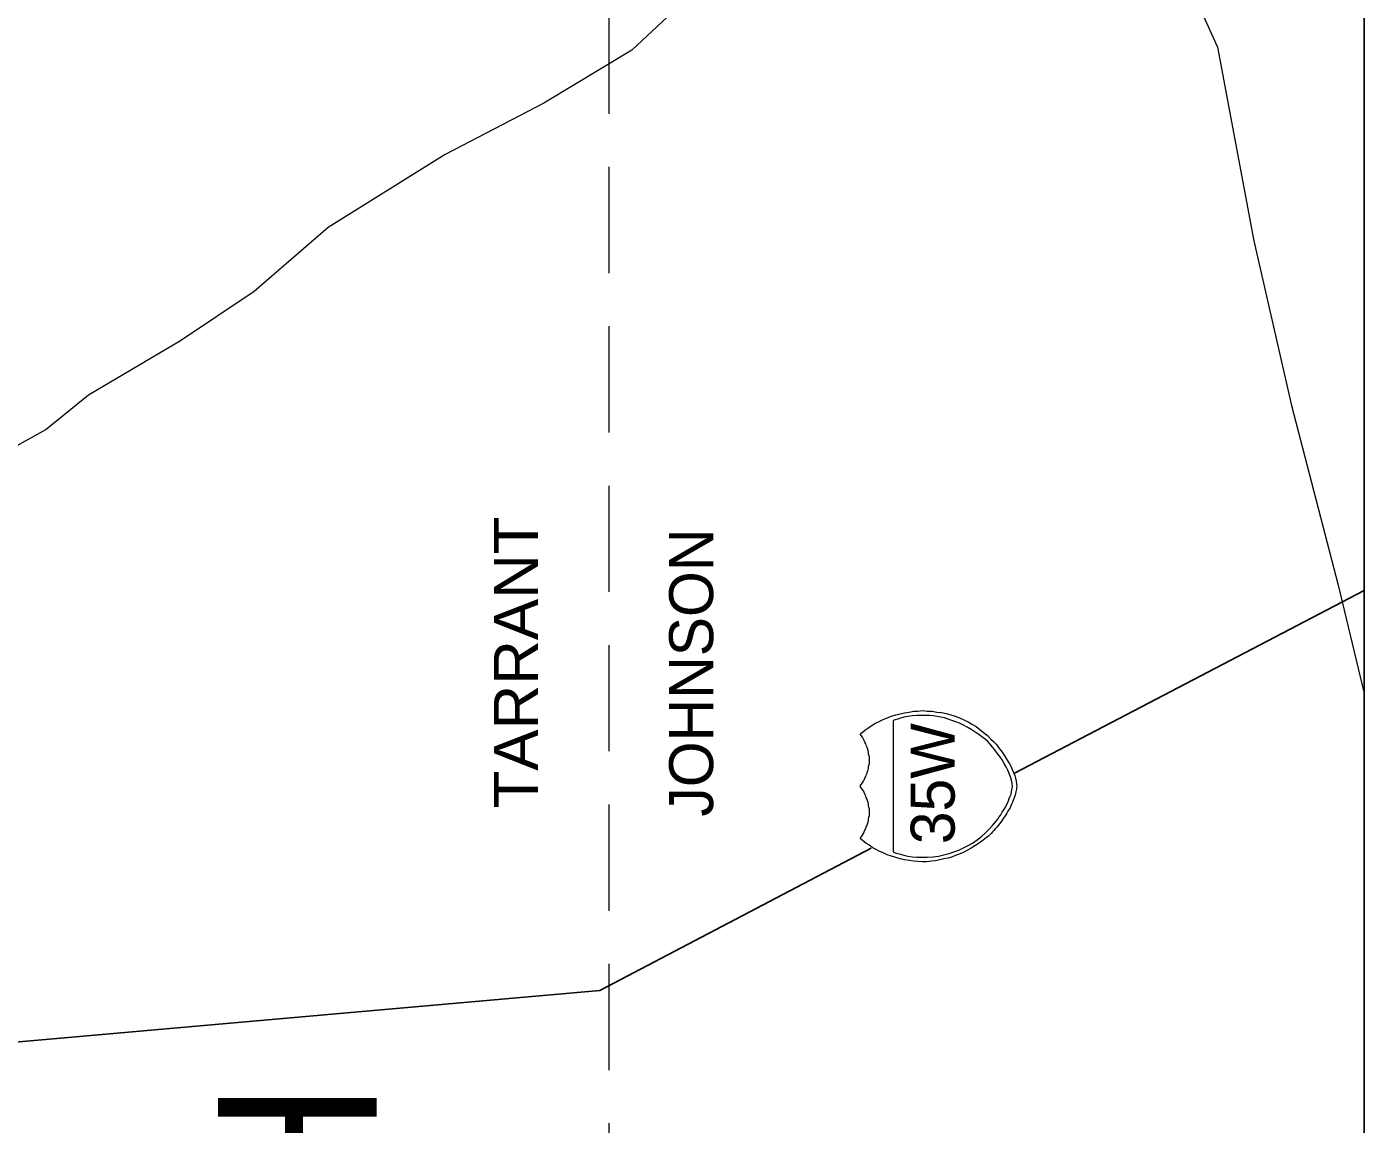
# Model space of a CAD drawing. Extents: x 2363323 to 2367082, y 6956018 to 6980837.
# Drawn here: x 2366064.3 to 2366219.2, y 6980582.6 to 6980709.7 of the extents above; entities that cross this region are included whole.
import ezdxf

# ---------------------------------------------------------------- set-up
doc = ezdxf.new("R2010")
doc.units = 0
doc.header["$LTSCALE"] = 4.1
doc.linetypes.add('MEDIUM_DASHED', pattern=[4.5, 3, -1.5])
doc.layers.add('62', color=7, linetype='Continuous', lineweight=13)
doc.layers.add('63', color=7, linetype='Continuous', lineweight=13)

msp = doc.modelspace()

# ---------------------------------------------------------------- linework, layer by layer
at = {"layer": '62', "linetype": 'MEDIUM_DASHED'}
msp.add_line((2366131.806, 6980385.954), (2366131.805, 6980835.548), dxfattribs=at)
at = {"layer": '62', "lineweight": 25}
msp.add_line((2366178.725, 6980623.262), (2366219.249, 6980644.436), dxfattribs=at)
for points in [[(2365753.976, 6980385.954), (2366219.249, 6980385.954), (2366219.249, 6980835.546), (2365753.974, 6980835.546)], [(2365954.874, 6980590.182), (2366003.705, 6980591.15), (2366059.484, 6980591.828), (2366130.702, 6980598.128), (2366162.138, 6980614.575)]]:
    msp.add_lwpolyline(points, dxfattribs=at)
at = {"layer": '62'}
for points in [[(2366094.97, 6980793.962), (2366103.882, 6980788.406), (2366120.534, 6980778.952), (2366139.278, 6980772.878), (2366153.61, 6980769.728), (2366166.728, 6980753.031), (2366176.79, 6980752.894), (2366186.194, 6980736.56), (2366195.014, 6980723.396), (2366202.238, 6980707.329), (2366206.47, 6980684.916), (2366210.836, 6980665.836), (2366216.234, 6980645.043), (2366219.25, 6980632.51)], [(2366168.8, 6980776.882), (2366165.783, 6980768.805), (2366163.94, 6980759.174), (2366160.383, 6980741.87), (2366154.128, 6980731.611), (2366149.72, 6980724.7), (2366143.802, 6980715.788), (2366134.416, 6980706.992), (2366124.222, 6980700.849), (2366112.792, 6980694.908), (2366099.244, 6980686.448), (2366090.672, 6980679.021), (2366082.168, 6980673.328), (2366071.481, 6980667.05), (2366066.596, 6980663.068), (2366053.86, 6980656.002)], [(2366161.328, 6980622.518), (2366161.42, 6980622.699), (2366161.51, 6980622.902), (2366161.576, 6980623.06), (2366161.666, 6980623.262), (2366161.712, 6980623.464), (2366161.778, 6980623.644), (2366161.823, 6980623.824), (2366161.846, 6980624.025), (2366161.89, 6980624.206), (2366161.936, 6980624.409), (2366161.936, 6980624.589), (2366161.936, 6980624.793), (2366161.937, 6980624.972), (2366161.936, 6980625.15), (2366161.89, 6980625.376), (2366161.847, 6980625.534), (2366161.823, 6980625.714), (2366161.78, 6980625.916), (2366161.71, 6980626.119), (2366161.666, 6980626.299), (2366161.577, 6980626.502), (2366161.51, 6980626.682), (2366161.42, 6980626.862), (2366161.33, 6980627.042), (2366161.24, 6980627.222), (2366161.126, 6980627.424), (2366160.99, 6980627.626), (2366160.856, 6980627.808), (2366161.17, 6980628.076), (2366161.508, 6980628.326), (2366161.868, 6980628.572), (2366162.273, 6980628.818), (2366162.656, 6980629.046), (2366163.083, 6980629.27), (2366163.534, 6980629.473), (2366164.007, 6980629.676), (2366164.5, 6980629.856), (2366164.996, 6980630.013), (2366165.514, 6980630.146), (2366166.008, 6980630.26), (2366166.526, 6980630.35), (2366167.044, 6980630.44), (2366167.562, 6980630.463), (2366168.08, 6980630.51), (2366168.642, 6980630.464), (2366169.206, 6980630.44), (2366169.768, 6980630.352), (2366170.286, 6980630.282), (2366170.826, 6980630.194), (2366171.366, 6980630.013), (2366171.885, 6980629.856), (2366172.378, 6980629.676), (2366172.875, 6980629.45), (2366173.368, 6980629.204), (2366173.82, 6980628.933), (2366174.292, 6980628.662), (2366174.742, 6980628.326), (2366175.168, 6980627.986), (2366175.598, 6980627.628), (2366176.001, 6980627.222), (2366176.316, 6980626.929), (2366176.608, 6980626.616), (2366176.901, 6980626.254), (2366177.171, 6980625.916), (2366177.418, 6980625.534), (2366177.666, 6980625.15), (2366177.892, 6980624.79), (2366178.116, 6980624.432), (2366178.318, 6980624.072), (2366178.478, 6980623.712), (2366178.634, 6980623.352), (2366178.77, 6980622.993), (2366178.86, 6980622.676), (2366178.926, 6980622.362), (2366178.971, 6980622.046), (2366178.995, 6980621.776)], [(2366178.995, 6980621.776), (2366178.971, 6980621.596), (2366178.971, 6980621.439), (2366178.95, 6980621.259), (2366178.904, 6980621.103), (2366178.858, 6980620.922), (2366178.815, 6980620.742), (2366178.746, 6980620.516), (2366178.68, 6980620.312), (2366178.59, 6980620.134), (2366178.521, 6980619.932), (2366178.41, 6980619.704), (2366178.32, 6980619.502), (2366178.228, 6980619.278), (2366178.118, 6980619.099), (2366177.981, 6980618.871), (2366177.868, 6980618.648), (2366177.734, 6980618.445), (2366177.598, 6980618.22), (2366177.442, 6980618.019), (2366177.308, 6980617.816), (2366177.171, 6980617.612), (2366176.991, 6980617.412), (2366176.856, 6980617.208), (2366176.698, 6980617.028), (2366176.518, 6980616.826), (2366176.361, 6980616.645), (2366176.205, 6980616.465), (2366176.024, 6980616.308), (2366175.844, 6980616.105), (2366175.688, 6980615.948), (2366175.506, 6980615.812), (2366175.326, 6980615.655), (2366174.966, 6980615.385), (2366174.537, 6980615.092), (2366174.134, 6980614.846), (2366173.728, 6980614.599), (2366173.302, 6980614.352), (2366172.875, 6980614.125), (2366172.448, 6980613.924), (2366171.996, 6980613.766), (2366171.546, 6980613.585), (2366171.074, 6980613.428), (2366170.578, 6980613.338), (2366170.106, 6980613.225), (2366169.611, 6980613.112), (2366169.137, 6980613.068), (2366168.597, 6980613.024), (2366168.08, 6980612.998), (2366167.56, 6980613.045), (2366167.043, 6980613.09), (2366166.526, 6980613.158), (2366166.008, 6980613.246), (2366165.513, 6980613.36), (2366164.996, 6980613.495), (2366164.502, 6980613.652), (2366164.006, 6980613.81), (2366163.533, 6980614.036), (2366163.083, 6980614.236), (2366162.657, 6980614.462), (2366162.273, 6980614.686), (2366161.866, 6980614.958), (2366161.51, 6980615.16), (2366161.172, 6980615.43), (2366160.856, 6980615.7), (2366160.99, 6980615.88), (2366161.126, 6980616.082), (2366161.24, 6980616.285), (2366161.33, 6980616.465), (2366161.42, 6980616.668), (2366161.508, 6980616.848), (2366161.577, 6980617.05), (2366161.666, 6980617.232), (2366161.71, 6980617.41), (2366161.778, 6980617.59), (2366161.823, 6980617.792), (2366161.847, 6980617.972), (2366161.89, 6980618.199), (2366161.937, 6980618.355), (2366161.937, 6980618.536), (2366161.936, 6980618.76), (2366161.936, 6980618.94), (2366161.936, 6980619.12), (2366161.892, 6980619.322), (2366161.847, 6980619.502), (2366161.823, 6980619.682), (2366161.778, 6980619.862), (2366161.71, 6980620.088), (2366161.667, 6980620.269), (2366161.576, 6980620.449), (2366161.508, 6980620.629), (2366161.418, 6980620.832), (2366161.328, 6980621.034), (2366161.238, 6980621.214), (2366161.127, 6980621.394), (2366160.992, 6980621.576), (2366160.857, 6980621.776), (2366160.99, 6980621.956), (2366161.126, 6980622.136), (2366161.238, 6980622.34), (2366161.328, 6980622.518)]]:
    msp.add_lwpolyline(points, dxfattribs=at)
msp.add_lwpolyline([(2366164.703, 6980629.383), (2366164.704, 6980614.148), (2366164.928, 6980614.059), (2366165.22, 6980613.968), (2366165.534, 6980613.878), (2366165.942, 6980613.788), (2366166.392, 6980613.676), (2366166.908, 6980613.585), (2366167.448, 6980613.54), (2366168.081, 6980613.538), (2366168.687, 6980613.542), (2366169.342, 6980613.585), (2366169.948, 6980613.675), (2366170.556, 6980613.81), (2366171.164, 6980613.968), (2366171.726, 6980614.148), (2366172.311, 6980614.35), (2366172.851, 6980614.62), (2366173.368, 6980614.89), (2366173.886, 6980615.184), (2366174.404, 6980615.544), (2366174.898, 6980615.902), (2366175.347, 6980616.33), (2366175.8, 6980616.78), (2366176.205, 6980617.23), (2366176.608, 6980617.726), (2366176.812, 6980617.95), (2366176.97, 6980618.22), (2366177.172, 6980618.468), (2366177.33, 6980618.76), (2366177.488, 6980619.009), (2366177.666, 6980619.278), (2366177.778, 6980619.548), (2366177.936, 6980619.818), (2366178.05, 6980620.088), (2366178.138, 6980620.335), (2366178.252, 6980620.608), (2366178.342, 6980620.832), (2366178.41, 6980621.1), (2366178.454, 6980621.326), (2366178.476, 6980621.552), (2366178.498, 6980621.778), (2366178.476, 6980622.093), (2366178.41, 6980622.474), (2366178.275, 6980622.834), (2366178.138, 6980623.239), (2366177.982, 6980623.62), (2366177.778, 6980624.026), (2366177.554, 6980624.41), (2366177.308, 6980624.814), (2366177.036, 6980625.219), (2366176.744, 6980625.602), (2366176.475, 6980625.962), (2366176.205, 6980626.299), (2366175.935, 6980626.638), (2366175.642, 6980626.929), (2366175.348, 6980627.199), (2366175.101, 6980627.379), (2366174.628, 6980627.739), (2366174.178, 6980628.032), (2366173.73, 6980628.324), (2366173.258, 6980628.594), (2366172.828, 6980628.842), (2366172.378, 6980629.047), (2366171.952, 6980629.226), (2366171.502, 6980629.384), (2366171.074, 6980629.54), (2366170.648, 6980629.676), (2366170.218, 6980629.767), (2366169.77, 6980629.833), (2366169.341, 6980629.9), (2366168.914, 6980629.946), (2366168.484, 6980629.968), (2366168.081, 6980629.968), (2366167.448, 6980629.968), (2366166.91, 6980629.923), (2366166.39, 6980629.833), (2366165.942, 6980629.766), (2366165.536, 6980629.653), (2366165.22, 6980629.54), (2366164.928, 6980629.45)], close=True, dxfattribs=at)
at = {"layer": '63', "linetype": 'MEDIUM_DASHED'}
msp.add_line((2366131.806, 6980385.954), (2366131.805, 6980835.548), dxfattribs=at)
at = {"layer": '63', "lineweight": 25}
msp.add_line((2366178.725, 6980623.262), (2366219.249, 6980644.436), dxfattribs=at)
for points in [[(2365753.976, 6980385.954), (2366219.249, 6980385.954), (2366219.249, 6980835.546), (2365753.974, 6980835.546)], [(2365954.874, 6980590.182), (2366003.705, 6980591.15), (2366059.484, 6980591.828), (2366130.702, 6980598.128), (2366162.138, 6980614.575)]]:
    msp.add_lwpolyline(points, dxfattribs=at)
at = {"layer": '63'}
for points in [[(2366094.97, 6980793.962), (2366103.882, 6980788.406), (2366120.534, 6980778.952), (2366139.278, 6980772.878), (2366153.61, 6980769.728), (2366166.728, 6980753.031), (2366176.79, 6980752.894), (2366186.194, 6980736.56), (2366195.014, 6980723.396), (2366202.238, 6980707.329), (2366206.47, 6980684.916), (2366210.836, 6980665.836), (2366216.234, 6980645.043), (2366219.25, 6980632.51)], [(2366168.8, 6980776.882), (2366165.783, 6980768.805), (2366163.94, 6980759.174), (2366160.383, 6980741.87), (2366154.128, 6980731.611), (2366149.72, 6980724.7), (2366143.802, 6980715.788), (2366134.416, 6980706.992), (2366124.222, 6980700.849), (2366112.792, 6980694.908), (2366099.244, 6980686.448), (2366090.672, 6980679.021), (2366082.168, 6980673.328), (2366071.481, 6980667.05), (2366066.596, 6980663.068), (2366053.86, 6980656.002)], [(2366161.328, 6980622.518), (2366161.42, 6980622.699), (2366161.51, 6980622.902), (2366161.576, 6980623.06), (2366161.666, 6980623.262), (2366161.712, 6980623.464), (2366161.778, 6980623.644), (2366161.823, 6980623.824), (2366161.846, 6980624.025), (2366161.89, 6980624.206), (2366161.936, 6980624.409), (2366161.936, 6980624.589), (2366161.936, 6980624.793), (2366161.937, 6980624.972), (2366161.936, 6980625.15), (2366161.89, 6980625.376), (2366161.847, 6980625.534), (2366161.823, 6980625.714), (2366161.78, 6980625.916), (2366161.71, 6980626.119), (2366161.666, 6980626.299), (2366161.577, 6980626.502), (2366161.51, 6980626.682), (2366161.42, 6980626.862), (2366161.33, 6980627.042), (2366161.24, 6980627.222), (2366161.126, 6980627.424), (2366160.99, 6980627.626), (2366160.856, 6980627.808), (2366161.17, 6980628.076), (2366161.508, 6980628.326), (2366161.868, 6980628.572), (2366162.273, 6980628.818), (2366162.656, 6980629.046), (2366163.083, 6980629.27), (2366163.534, 6980629.473), (2366164.007, 6980629.676), (2366164.5, 6980629.856), (2366164.996, 6980630.013), (2366165.514, 6980630.146), (2366166.008, 6980630.26), (2366166.526, 6980630.35), (2366167.044, 6980630.44), (2366167.562, 6980630.463), (2366168.08, 6980630.51), (2366168.642, 6980630.464), (2366169.206, 6980630.44), (2366169.768, 6980630.352), (2366170.286, 6980630.282), (2366170.826, 6980630.194), (2366171.366, 6980630.013), (2366171.885, 6980629.856), (2366172.378, 6980629.676), (2366172.875, 6980629.45), (2366173.368, 6980629.204), (2366173.82, 6980628.933), (2366174.292, 6980628.662), (2366174.742, 6980628.326), (2366175.168, 6980627.986), (2366175.598, 6980627.628), (2366176.001, 6980627.222), (2366176.316, 6980626.929), (2366176.608, 6980626.616), (2366176.901, 6980626.254), (2366177.171, 6980625.916), (2366177.418, 6980625.534), (2366177.666, 6980625.15), (2366177.892, 6980624.79), (2366178.116, 6980624.432), (2366178.318, 6980624.072), (2366178.478, 6980623.712), (2366178.634, 6980623.352), (2366178.77, 6980622.993), (2366178.86, 6980622.676), (2366178.926, 6980622.362), (2366178.971, 6980622.046), (2366178.995, 6980621.776)], [(2366178.995, 6980621.776), (2366178.971, 6980621.596), (2366178.971, 6980621.439), (2366178.95, 6980621.259), (2366178.904, 6980621.103), (2366178.858, 6980620.922), (2366178.815, 6980620.742), (2366178.746, 6980620.516), (2366178.68, 6980620.312), (2366178.59, 6980620.134), (2366178.521, 6980619.932), (2366178.41, 6980619.704), (2366178.32, 6980619.502), (2366178.228, 6980619.278), (2366178.118, 6980619.099), (2366177.981, 6980618.871), (2366177.868, 6980618.648), (2366177.734, 6980618.445), (2366177.598, 6980618.22), (2366177.442, 6980618.019), (2366177.308, 6980617.816), (2366177.171, 6980617.612), (2366176.991, 6980617.412), (2366176.856, 6980617.208), (2366176.698, 6980617.028), (2366176.518, 6980616.826), (2366176.361, 6980616.645), (2366176.205, 6980616.465), (2366176.024, 6980616.308), (2366175.844, 6980616.105), (2366175.688, 6980615.948), (2366175.506, 6980615.812), (2366175.326, 6980615.655), (2366174.966, 6980615.385), (2366174.537, 6980615.092), (2366174.134, 6980614.846), (2366173.728, 6980614.599), (2366173.302, 6980614.352), (2366172.875, 6980614.125), (2366172.448, 6980613.924), (2366171.996, 6980613.766), (2366171.546, 6980613.585), (2366171.074, 6980613.428), (2366170.578, 6980613.338), (2366170.106, 6980613.225), (2366169.611, 6980613.112), (2366169.137, 6980613.068), (2366168.597, 6980613.024), (2366168.08, 6980612.998), (2366167.56, 6980613.045), (2366167.043, 6980613.09), (2366166.526, 6980613.158), (2366166.008, 6980613.246), (2366165.513, 6980613.36), (2366164.996, 6980613.495), (2366164.502, 6980613.652), (2366164.006, 6980613.81), (2366163.533, 6980614.036), (2366163.083, 6980614.236), (2366162.657, 6980614.462), (2366162.273, 6980614.686), (2366161.866, 6980614.958), (2366161.51, 6980615.16), (2366161.172, 6980615.43), (2366160.856, 6980615.7), (2366160.99, 6980615.88), (2366161.126, 6980616.082), (2366161.24, 6980616.285), (2366161.33, 6980616.465), (2366161.42, 6980616.668), (2366161.508, 6980616.848), (2366161.577, 6980617.05), (2366161.666, 6980617.232), (2366161.71, 6980617.41), (2366161.778, 6980617.59), (2366161.823, 6980617.792), (2366161.847, 6980617.972), (2366161.89, 6980618.199), (2366161.937, 6980618.355), (2366161.937, 6980618.536), (2366161.936, 6980618.76), (2366161.936, 6980618.94), (2366161.936, 6980619.12), (2366161.892, 6980619.322), (2366161.847, 6980619.502), (2366161.823, 6980619.682), (2366161.778, 6980619.862), (2366161.71, 6980620.088), (2366161.667, 6980620.269), (2366161.576, 6980620.449), (2366161.508, 6980620.629), (2366161.418, 6980620.832), (2366161.328, 6980621.034), (2366161.238, 6980621.214), (2366161.127, 6980621.394), (2366160.992, 6980621.576), (2366160.857, 6980621.776), (2366160.99, 6980621.956), (2366161.126, 6980622.136), (2366161.238, 6980622.34), (2366161.328, 6980622.518)]]:
    msp.add_lwpolyline(points, dxfattribs=at)
msp.add_lwpolyline([(2366164.703, 6980629.383), (2366164.704, 6980614.148), (2366164.928, 6980614.059), (2366165.22, 6980613.968), (2366165.534, 6980613.878), (2366165.942, 6980613.788), (2366166.392, 6980613.676), (2366166.908, 6980613.585), (2366167.448, 6980613.54), (2366168.081, 6980613.538), (2366168.687, 6980613.542), (2366169.342, 6980613.585), (2366169.948, 6980613.675), (2366170.556, 6980613.81), (2366171.164, 6980613.968), (2366171.726, 6980614.148), (2366172.311, 6980614.35), (2366172.851, 6980614.62), (2366173.368, 6980614.89), (2366173.886, 6980615.184), (2366174.404, 6980615.544), (2366174.898, 6980615.902), (2366175.347, 6980616.33), (2366175.8, 6980616.78), (2366176.205, 6980617.23), (2366176.608, 6980617.726), (2366176.812, 6980617.95), (2366176.97, 6980618.22), (2366177.172, 6980618.468), (2366177.33, 6980618.76), (2366177.488, 6980619.009), (2366177.666, 6980619.278), (2366177.778, 6980619.548), (2366177.936, 6980619.818), (2366178.05, 6980620.088), (2366178.138, 6980620.335), (2366178.252, 6980620.608), (2366178.342, 6980620.832), (2366178.41, 6980621.1), (2366178.454, 6980621.326), (2366178.476, 6980621.552), (2366178.498, 6980621.778), (2366178.476, 6980622.093), (2366178.41, 6980622.474), (2366178.275, 6980622.834), (2366178.138, 6980623.239), (2366177.982, 6980623.62), (2366177.778, 6980624.026), (2366177.554, 6980624.41), (2366177.308, 6980624.814), (2366177.036, 6980625.219), (2366176.744, 6980625.602), (2366176.475, 6980625.962), (2366176.205, 6980626.299), (2366175.935, 6980626.638), (2366175.642, 6980626.929), (2366175.348, 6980627.199), (2366175.101, 6980627.379), (2366174.628, 6980627.739), (2366174.178, 6980628.032), (2366173.73, 6980628.324), (2366173.258, 6980628.594), (2366172.828, 6980628.842), (2366172.378, 6980629.047), (2366171.952, 6980629.226), (2366171.502, 6980629.384), (2366171.074, 6980629.54), (2366170.648, 6980629.676), (2366170.218, 6980629.767), (2366169.77, 6980629.833), (2366169.341, 6980629.9), (2366168.914, 6980629.946), (2366168.484, 6980629.968), (2366168.081, 6980629.968), (2366167.448, 6980629.968), (2366166.91, 6980629.923), (2366166.39, 6980629.833), (2366165.942, 6980629.766), (2366165.536, 6980629.653), (2366165.22, 6980629.54), (2366164.928, 6980629.45)], close=True, dxfattribs=at)

# ---------------------------------------------------------------- texts
at = {"layer": '62'}
for s, height, width, p in [('TARRANT', 5.099, 1.05, (2366123.547, 6980619.186)), ('WORTH', 18.39, 0.95, (2366104.871, 6980499.342))]:
    msp.add_text(s, height=height, rotation=90, dxfattribs=dict(at, width=width)).set_placement(p)
for s, p in [('JOHNSON', (2366143.845, 6980618.242)), ('35W', (2366171.817, 6980615.048))]:
    msp.add_text(s, height=5.099, rotation=90, dxfattribs=at).set_placement(p)
at = {"layer": '63'}
for s, height, width, p in [('TARRANT', 5.099, 1.05, (2366123.547, 6980619.186)), ('WORTH', 18.39, 0.95, (2366104.871, 6980499.342))]:
    msp.add_text(s, height=height, rotation=90, dxfattribs=dict(at, width=width)).set_placement(p)
for s, p in [('JOHNSON', (2366143.845, 6980618.242)), ('35W', (2366171.817, 6980615.048))]:
    msp.add_text(s, height=5.099, rotation=90, dxfattribs=at).set_placement(p)

doc.saveas('drawing.dxf')
